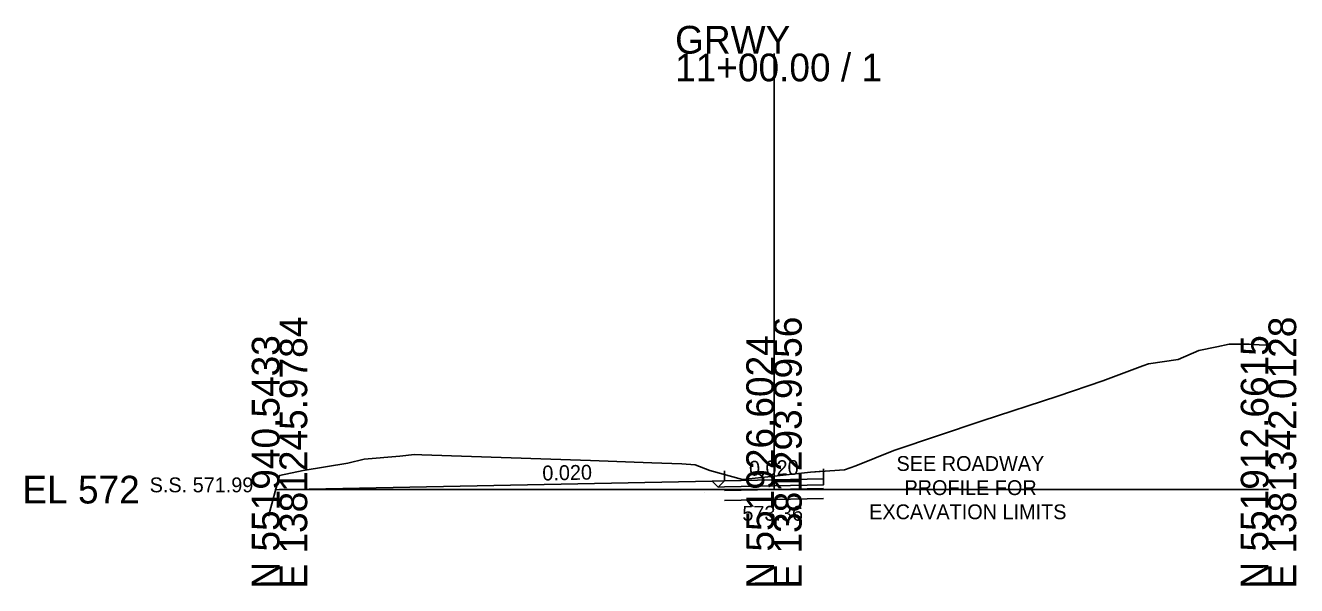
# Model space of a CAD drawing. Extents: x -26 to 103, y -10 to 3028.
# Drawn here: x -25.7 to 102.8, y 990.3 to 1046.9 of the extents above; entities that cross this region are included whole.
import ezdxf

# ---------------------------------------------------------------- set-up
doc = ezdxf.new("R2010")
doc.units = 0
for name, color, linetype in [('Exist Cross Section Cell', 7, 'Continuous'), ('Exist XS Center Line Elevation Label', 7, 'Continuous'), ('Exist XS Ground Line', 7, 'Continuous'), ('Prop XS Dump Level', 7, 'Continuous'), ('Prop XS Earthwork Shape', 7, 'Continuous'), ('Prop XS EOT Tick Mark', 7, 'Continuous'), ('Prop XS Finish Grade', 7, 'Continuous'), ('Prop XS Finish Grade Earthwork', 7, 'Continuous'), ('Prop XS Finish Grade Pavement', 7, 'Continuous'), ('Prop XS Pvmt Edge Slope', 7, 'Continuous'), ('Prop XS SE Text', 7, 'Continuous'), ('Prop XS SS Elevation Text', 7, 'Continuous'), ('Prop XS Subgrade Earthwork', 7, 'Continuous'), ('Prop XSC Text', 7, 'Continuous')]:
    doc.layers.add(name, color=color, linetype=linetype)

msp = doc.modelspace()

# ---------------------------------------------------------------- linework, layer by layer
at = {"layer": 'Exist Cross Section Cell'}
for p, q in [((50, 1000), (50, 1044.06)), ((0, 1000), (50, 1000)), ((50, 1000), (100, 1000))]:
    msp.add_line(p, q, dxfattribs=at)
at = {"layer": 'Exist XS Ground Line'}
for p, q in [((92.94, 1014.07), (94.76, 1014.43)), ((94.76, 1014.43), (96.01, 1014.69)), ((96.01, 1014.69), (98.05, 1014.69)), ((98.05, 1014.69), (99.07, 1014.63)), ((99.07, 1014.63), (100, 1014.61)), ((87.86, 1012.7), (90.88, 1013.15)), ((90.88, 1013.15), (92.94, 1014.07)), ((83.25, 1011.01), (87.3, 1012.5)), ((87.3, 1012.5), (87.86, 1012.7)), ((78.71, 1009.44), (83.25, 1011.01)), ((71.04, 1006.96), (78.71, 1009.44)), ((62.11, 1003.97), (71.04, 1006.96)), ((58.26, 1002.41), (62.11, 1003.97)), ((2.4, 1001.92), (6.9, 1002.68)), ((6.9, 1002.68), (8.57, 1003.07)), ((8.57, 1003.07), (12.18, 1003.38)), ((12.18, 1003.38), (13.66, 1003.54)), ((13.66, 1003.54), (14.4, 1003.51)), ((14.4, 1003.51), (31.45, 1002.94)), ((31.45, 1002.94), (37.64, 1002.71)), ((37.64, 1002.71), (40.67, 1002.6)), ((40.67, 1002.6), (42.04, 1002.5)), ((-1.11, 997.33), (0, 1001.44)), ((0, 1001.44), (2.4, 1001.92)), ((42.04, 1002.5), (43.5, 1001.94)), ((43.5, 1001.94), (46.81, 1001.03)), ((46.81, 1001.03), (50, 1001.36)), ((50, 1001.36), (53.68, 1001.75)), ((53.68, 1001.75), (57.13, 1002)), ((57.13, 1002), (58.26, 1002.41))]:
    msp.add_line(p, q, dxfattribs=at)
at = {"layer": 'Prop XS Dump Level'}
for p, q in [((45, 999.9), (50, 1000)), ((50, 1000), (55, 1000.1)), ((45, 998.9), (50, 999)), ((50, 999), (55, 999.1))]:
    msp.add_line(p, q, dxfattribs=at)
at = {"layer": 'Prop XS Earthwork Shape'}
msp.add_lwpolyline([(-0.39, 999.99), (0, 1001.44), (2.4, 1001.92), (6.9, 1002.68), (8.57, 1003.07), (12.18, 1003.38), (13.66, 1003.54), (14.4, 1003.51), (31.45, 1002.94), (37.64, 1002.71), (40.67, 1002.6), (42.04, 1002.5), (43.5, 1001.94), (46.81, 1001.03), (50, 1001.36), (53.68, 1001.75), (55, 1001.85), (55, 1000.48), (50, 1000.38), (45, 1000.28), (44.36, 1000.26), (43.75, 1000.87)], close=True, dxfattribs=at)
at = {"layer": 'Prop XS EOT Tick Mark'}
for p, q in [((45, 1000.9), (45, 1001.9)), ((55, 1001.1), (55, 1002.1))]:
    msp.add_line(p, q, dxfattribs=at)
at = {"layer": 'Prop XS Finish Grade'}
msp.add_line((45, 1000.9), (43.75, 1000.87), dxfattribs=at)
at = {"layer": 'Prop XS Finish Grade Earthwork'}
msp.add_line((43.75, 1000.87), (-0.39, 999.99), dxfattribs=at)
at = {"layer": 'Prop XS Finish Grade Pavement'}
for p, q in [((45, 1000.9), (50, 1001)), ((50, 1001), (55, 1001.1))]:
    msp.add_line(p, q, dxfattribs=at)
at = {"layer": 'Prop XS Pvmt Edge Slope'}
msp.add_line((45, 1000.9), (44.36, 1000.26), dxfattribs=at)
at = {"layer": 'Prop XS Subgrade Earthwork'}
for p, q in [((55, 1000.48), (55, 1001.85)), ((44.36, 1000.26), (43.75, 1000.87)), ((45, 1000.28), (44.36, 1000.26)), ((50, 1000.38), (45, 1000.28)), ((55, 1000.48), (50, 1000.38))]:
    msp.add_line(p, q, dxfattribs=at)

# ---------------------------------------------------------------- texts
at = {"layer": 'Exist Cross Section Cell'}
for s, p in [('GRWY', (40, 1044.06)), ('11+00.00 / 1', (40, 1041.26)), ('EL 572', (-26, 998.6))]:
    msp.add_text(s, height=2.8, dxfattribs=at).set_placement(p)
for s, p in [('E 1381245.9784', (2.8, 990)), ('E 1381293.9956', (52.8, 990)), ('E 1381342.0128', (102.8, 990)), ('N 551940.5433', (0, 990)), ('N 551926.6024', (50, 990)), ('N 551912.6615', (100, 990))]:
    msp.add_text(s, height=2.8, rotation=90, dxfattribs=at).set_placement(p)
at = {"layer": 'Exist XS Center Line Elevation Label'}
msp.add_text('573.36', height=1.5, dxfattribs=at).set_placement((46.8, 996.86))
at = {"layer": 'Prop XS Dump Level'}
for p in [(57, 999.98), (43, 999.7)]:
    msp.add_text('Case1', height=0.04, dxfattribs=at).set_placement(p)
at = {"layer": 'Prop XS SE Text'}
for p in [(47.49, 1001.4), (26.59, 1000.92)]:
    msp.add_text('0.020', height=1.5, rotation=1.1458, dxfattribs=at).set_placement(p)
at = {"layer": 'Prop XS SS Elevation Text'}
msp.add_text('S.S. 571.99', height=1.5, dxfattribs=at).set_placement((-13.13, 999.73))
at = {"layer": 'Prop XSC Text'}
for s, p in [('SEE ROADWAY', (62.39, 1001.89)), ('PROFILE FOR', (63.19, 999.45)), ('EXCAVATION LIMITS', (59.62, 997.01))]:
    msp.add_text(s, height=1.5, dxfattribs=at).set_placement(p)

doc.saveas('drawing.dxf')
